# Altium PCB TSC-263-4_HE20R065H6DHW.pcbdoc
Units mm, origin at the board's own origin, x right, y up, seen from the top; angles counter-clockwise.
Board outline 24.9 x 30.31 mm, 2 copper layers (Top Layer, Bottom Layer), stack 0.07 mm thick; 1 components, 0 nets, 4 pads, 0 vias.
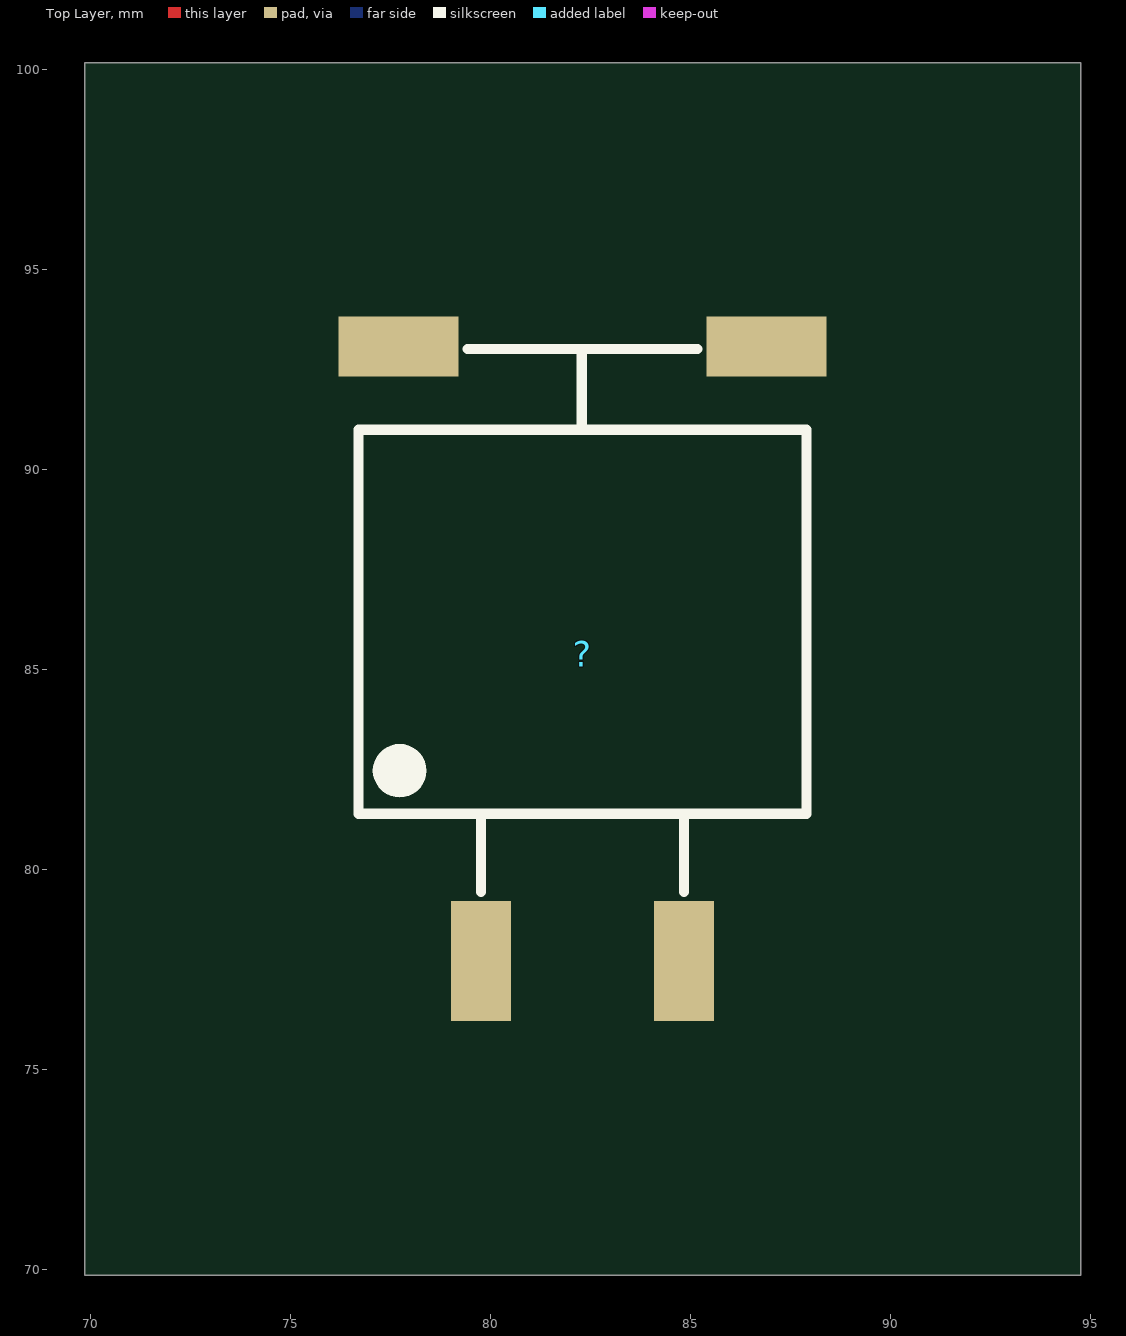
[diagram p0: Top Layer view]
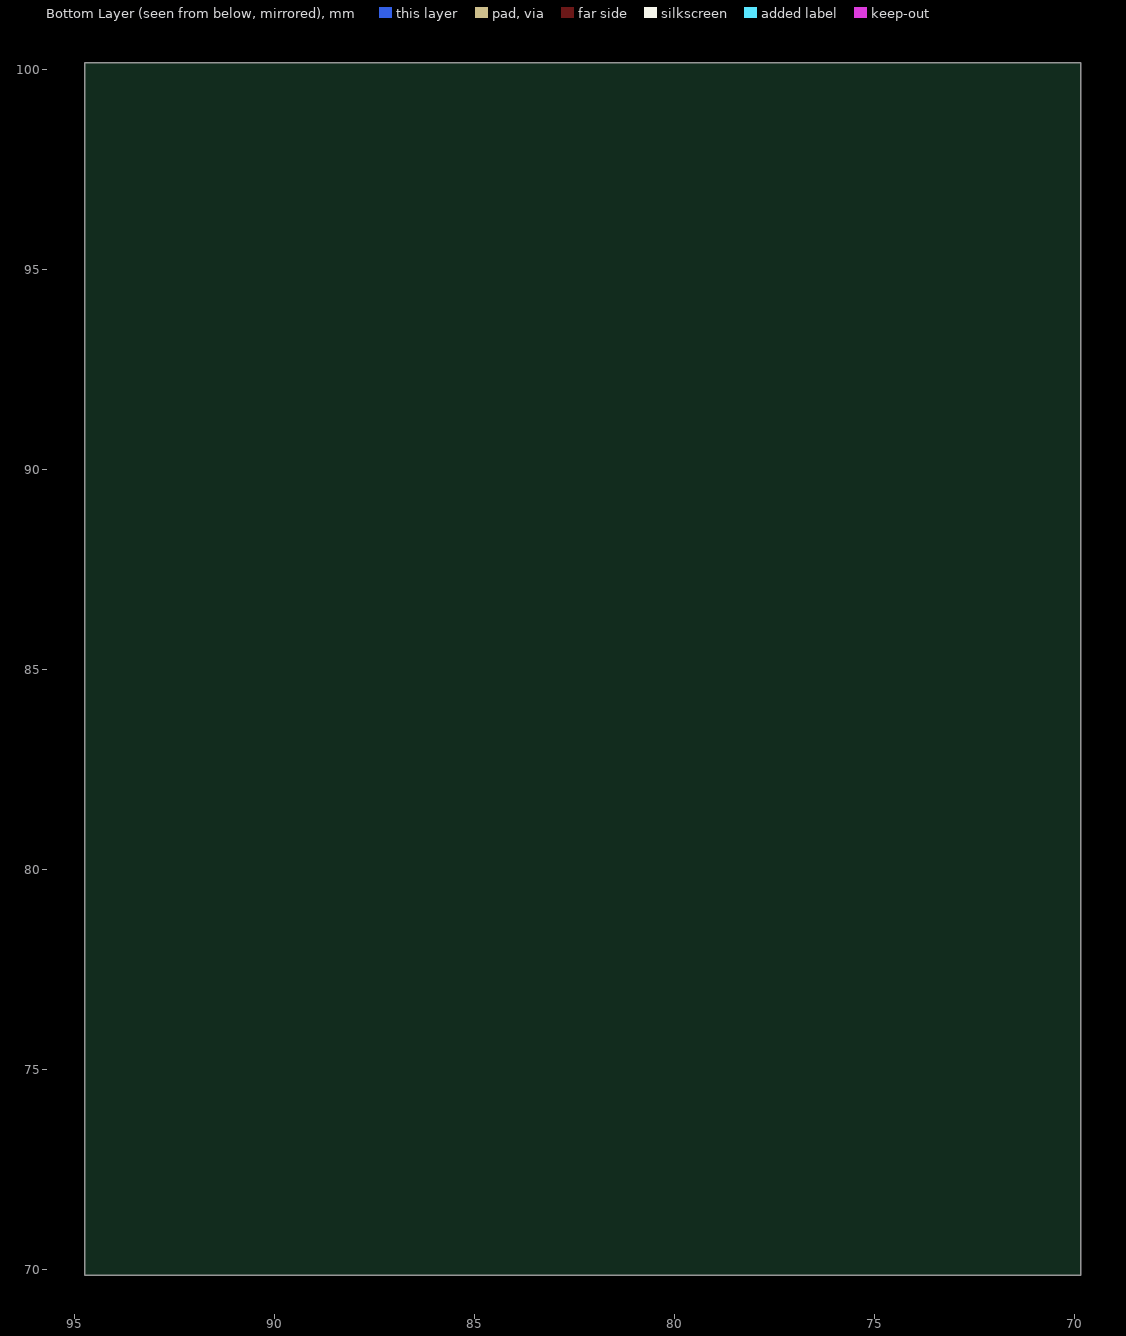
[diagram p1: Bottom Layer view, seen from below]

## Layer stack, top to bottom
Top Solder Mask Layer: solder mask 0.01, Dk 3.3
Top Layer: signal copper 0.035
Bottom Layer: signal copper 0.035
Bottom Solder Mask Layer: solder mask 0.01, Dk 3.3

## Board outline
94.75,69.85 69.85,69.85 69.85,100.165 94.75,100.165

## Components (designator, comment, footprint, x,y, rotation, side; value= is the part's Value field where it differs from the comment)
? "TSC-263-4_HE20R065H6DHW" TSC-263-4_HE20R065H6DHW 82.3,85.382 r0 top

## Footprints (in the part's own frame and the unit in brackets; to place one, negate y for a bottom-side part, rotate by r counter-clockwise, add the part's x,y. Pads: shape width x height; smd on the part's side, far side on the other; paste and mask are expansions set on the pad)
TSC-263-4_HE20R065H6DHW [mm]
  rect 1.5x3 smd paste+0 mask+0.051: 1(-2.54,-7.682) 2(2.54,-7.682)
  rect 3x1.5 smd paste+0 mask+0.051: 3(-4.6,7.682) 4(4.6,7.682)
  silkscreen extent -5.6,-5.95 5.6,7.62

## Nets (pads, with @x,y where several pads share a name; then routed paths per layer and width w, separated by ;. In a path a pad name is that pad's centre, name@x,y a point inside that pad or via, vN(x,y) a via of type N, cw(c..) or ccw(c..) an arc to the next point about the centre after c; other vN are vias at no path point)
pads on no net: ?.1 ?.2 ?.3 ?.4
